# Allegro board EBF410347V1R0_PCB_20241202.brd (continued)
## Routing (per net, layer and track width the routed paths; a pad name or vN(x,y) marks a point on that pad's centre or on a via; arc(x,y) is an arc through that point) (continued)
UART4_TX_M0: length 81.6
  TOP w0.173: v1(106.78,44.14) R128.1 107.38,44.91 D72.1 108.69,43.6 110.19,43.6 110.56,43.22 U25.11 ; J3.68 66.79,67.7 66.4,67.31 v1(66.4,67.26)
  ART03 w0.16: v1(65.47,48.61) 64.79,48.61 64.47,48.93 64.47,66.06 65.17,66.77 65.91,66.77 v1(66.4,67.26)
  BOTTOM w0.173: v1(65.47,48.61) 65.45,48.64 64.59,48.64 64.26,48.31 64.26,45.52 64.44,45.34 67.39,45.34 67.59,45.54 67.59,46.23 67.76,46.4 89.1,46.4 89.89,45.62 92.91,45.62 93.75,44.78 93.75,42.8 94.16,42.39 101.45,42.39 101.83,42.77 101.83,43.84 102.14,44.14 v1(106.78,44.14)
UART7_RX_M0: length 75.4
  TOP w0.173: U25.9 113.1,44.21 D69.1 112.46,44.91 R123.1 v1(111.86,44.14) ; v1(66.35,66.27) 66.35,66.56 65.89,67.03 J3.69
  ART03 w0.16: v1(65.47,49.61) 65.47,65.32 66.35,66.2 v1(66.35,66.27)
  BOTTOM w0.173: v1(65.47,49.61) 66.44,49.61 67.44,48.61 108.94,48.61 109.68,47.88 110.7,47.88 111.2,47.37 111.2,44.8 v1(111.86,44.14)
UART7_TX_M0: length 76.2
  TOP w0.173: U25.10 111.84,42.99 D70.1 109.92,44.91 R124.1 v1(109.32,44.14) ; J3.70 64.99,67.63 v1(65.35,67.27)
  ART03 w0.16: v1(65.35,67.27) 65.13,67.27 64.06,66.19 64.06,48.53 64.48,48.11 65.97,48.11 v1(66.47,48.61)
  BOTTOM w0.173: v1(66.47,48.61) 66.83,48.26 107.9,48.26 108.28,47.88 108.28,46.61 109.32,45.57 v1(109.32,44.14)
UART8_RX_M0: length 99.5
  TOP w0.173: J3.71 64.09,67.54 63.8,67.26 62.22,67.26 v1(62.21,67.25)
  ART03 w0.16: v1(97.12,12.57) 93.79,12.57 93.47,12.89 93.47,15.75 93.09,16.13 67.82,16.13 67.41,15.72 64.41,15.72 64.06,16.08 64.06,25.35 61.79,27.61 61.79,66.54 62.21,66.96 v1(62.21,67.25)
  BOTTOM w0.173: v1(97.12,12.57) 97.66,13.11 99.28,13.11 R115.1
  BOTTOM w0.254: U24.1 D60.1 99.81,11.85 R115.1
UART8_TX_M0: length 94.4
  TOP w0.173: J3.72 63.19,68.45 v1(63.39,68.25)
  ART03 w0.16: v1(97.1,17.76) 83.42,17.76 82.35,16.69 64.83,16.69 64.51,17.01 64.51,25.61 62.31,27.81 62.31,66.61 63.39,67.7 v1(63.39,68.25)
  BOTTOM w0.173: v1(97.1,17.76) 99.51,17.76 99.81,17.46 R117.1
  BOTTOM w0.254: R117.1 99.81,16.04 D61.1 100.87,14.98 U24.4
UART9_RX_M1: length 84.8
  TOP w0.173: v1(61.21,67.25) 61.39,67.25 62.29,68.15 J3.73
  ART03 w0.16: v1(82.69,12.57) 82.69,13.44 82.19,13.94 71.07,13.94 70.73,13.6 69.81,13.6 69.39,14.02 68.17,14.02 67.94,13.79 63.68,13.79 63.12,14.35 63.12,17.78 62.64,18.26 62.64,25.35 60.79,27.19 60.79,66.81 61.21,67.23 v1(61.21,67.25)
  BOTTOM w0.173: R125.1 84.95,13.11 83.23,13.11 v1(82.69,12.57)
  BOTTOM w0.254: R125.1 85.49,11.85 D67.1 U26.1
UART9_TX_M1: length 82.7
  TOP w0.173: v1(61.21,68.25) 61.39,68.43 J3.74
  ART03 w0.16: v1(82.93,15.37) 68.2,15.37 67.49,14.65 63.96,14.65 63.64,14.97 63.64,25.08 61.28,27.44 61.28,66.59 61.72,67.03 61.72,67.72 61.21,68.23 v1(61.21,68.25)
  BOTTOM w0.173: v1(82.93,15.37) 82.93,15.87 83.19,16.13 84.85,16.13 R127.1
  BOTTOM w0.254: U26.4 86.54,14.98 D68.1 86.16,16.09 R127.1
USB20_HOST1_DM: length 55.3
  TOP w0.132: J3.94 43.39,70.45 43.72,70.78 43.72,71.23 44.06,71.58 91.87,71.58 92.53,70.92 92.53,67.31 R65.2
USB20_HOST1_DP: length 55.4
  TOP w0.132: R64.2 92.29,67.31 92.29,70.82 91.77,71.34 91.46,71.34 91.24,71.12 90.93,71.12 90.72,71.34 90.41,71.34 90.19,71.12 89.88,71.12 89.66,71.34 89.35,71.34 89.13,71.12 88.82,71.12 88.6,71.34 88.29,71.34 88.07,71.12 87.76,71.12 87.55,71.34 87.24,71.34 87.02,71.12 86.71,71.12 86.49,71.34 44.16,71.34 43.96,71.14 43.96,70.78 44.29,70.45 J3.93
USB20_HUB_PWR_EN: length 35.9
  TOP w0.173: J3.42 82.76,60.3 v1(82.65,60.19) ; R67.1 v1(110.31,53.2)
  BOTTOM w0.173: v1(110.31,53.2) 109.54,53.97 105.28,53.97 104.77,53.46 96.83,53.46 96.14,54.15 92.86,54.15 92.46,54.56 92.46,55.88 92.13,56.21 83.87,56.21 83.36,56.72 83.36,59.48 v1(82.65,60.19)
USB30_DM: length 18.8
  BOTTOM w0.132: R52.1 72.7,67.54 72.84,67.67 72.84,69.91 72.67,70.08 ; 72.67,70.08 72.84,70.25 72.84,71.33 72.71,71.46 70.97,71.46 70.56,71.87 70.56,75.37 71.61,76.42 75.93,76.42 76.29,76.06 76.29,75.3 76.42,75.17 J9.2 ; 72.67,70.08 D17.1
USB30_DP: length 18.6
  BOTTOM w0.132: 73.25,70.08 73.08,69.91 73.08,67.67 73.21,67.54 R53.1 ; 73.25,70.08 73.08,70.24 73.08,71.43 72.81,71.7 72.33,71.7 72.12,71.91 71.75,71.91 71.54,71.7 71.07,71.7 70.8,71.97 70.8,72.25 70.99,72.44 70.99,72.78 70.8,72.97 70.8,73.31 70.99,73.5 70.99,73.84 70.8,74.03 70.8,75.27 71.71,76.18 75.83,76.18 76.05,75.96 76.05,75.3 75.92,75.17 J9.3 ; 73.25,70.08 D18.1
USB30_OTG0_DM: length 50.5
  TOP w0.132: J3.97 40.69,68.54 41.02,68.21 41.02,67.08 41.38,66.72 44.82,66.72 45.09,66.46 45.09,60.71 45.55,60.24 73.99,60.24 v1(74.37,59.86)
  BOTTOM w0.132: R52.2 72.26,66.09 72.4,65.95 72.71,65.95 72.84,65.82 72.84,60.52 73.13,60.24 73.99,60.24 v1(74.37,59.86)
USB30_OTG0_DP: length 50.8
  TOP w0.132: J3.96 41.59,68.54 41.26,68.21 41.26,67.18 41.48,66.96 44.92,66.96 45.32,66.56 45.32,60.8 45.65,60.48 74.24,60.48 74.37,60.61 v1(74.37,60.86)
  BOTTOM w0.132: R53.2 73.66,66.09 73.53,65.95 73.21,65.95 73.08,65.82 73.08,64.8 73.3,64.58 73.3,64.28 73.08,64.05 73.08,63.75 73.3,63.52 73.3,63.22 73.08,63 73.08,62.69 73.3,62.47 73.3,62.16 73.08,61.94 73.08,61.63 73.3,61.41 73.3,61.11 73.08,60.88 73.08,60.62 73.23,60.48 74.24,60.48 74.37,60.61 v1(74.37,60.86)
USB30_OTG0_ID: length 54.3
  TOP w0.173: J3.99 38.89,72.58 39.23,72.92 47.69,72.92 48.67,73.9 48.67,76.77 48.98,77.09 51.93,77.09 52.63,77.79 52.63,80.44 54.14,81.95 81.13,81.95 v1(81.9,81.19)
  BOTTOM w0.173: v1(81.9,81.19) 81.92,81.2 R193.2
USB30_OTG0_SSRXN: length 37.5
  TOP w0.132: v1(75.07,63.16) 48.62,63.16 48.22,63.56 48.22,68.21 47.89,68.54 J3.89
  BOTTOM w0.132: R54.2 74.8,66.09 74.94,65.95 75.25,65.95 75.38,65.82 75.38,65.56 75.16,65.34 75.16,65.03 75.38,64.81 75.38,64.51 75.16,64.28 75.16,63.98 75.38,63.75 75.38,63.29 75.25,63.16 v1(75.07,63.16)
USB30_OTG0_SSRXP: length 37.8
  TOP w0.132: J3.88 48.79,68.54 48.46,68.21 48.46,63.66 48.72,63.4 74.64,63.4 74.89,63.64 75.27,63.64 75.75,63.16 v1(75.93,63.16)
  BOTTOM w0.132: v1(75.93,63.16) 75.62,63.47 75.62,65.82 75.75,65.95 76.07,65.95 76.2,66.09 R55.2
USB30_OTG0_SSTXN: length 45.9
  TOP w0.132: v1(77.56,62.65) 77.87,62.96 77.87,63.31 77.74,63.44 77.09,63.44 76.92,63.27 76.92,62.09 76.49,61.66 46.82,61.66 46.42,62.06 46.42,68.21 46.09,68.54 J3.91
  BOTTOM w0.132: C63.2 77.34,66.09 77.48,65.95 77.74,65.95 77.89,65.8 77.89,62.98 v1(77.56,62.65)
USB30_OTG0_SSTXP: length 45.9
  TOP w0.132: J3.90 46.99,68.54 46.66,68.21 46.66,62.16 46.92,61.9 76.39,61.9 76.68,62.19 76.68,63.37 76.99,63.68 77.84,63.68 78.11,63.4 78.11,62.96 v1(78.42,62.65)
  BOTTOM w0.132: C64.2 78.74,66.09 78.61,65.95 78.31,65.95 78.13,65.77 78.13,62.94 v1(78.42,62.65)
USB30_OTG0_VBUSDET: length 54.9
  TOP w0.173: v1(79.88,83.63) 79.31,83.06 74.12,83.06 73.63,82.57 53.87,82.57 52.04,80.75 52.04,78.03 51.69,77.67 48.74,77.67 48.08,77.01 48.08,74.14 47.45,73.51 38.33,73.51 37.99,73.16 J3.100
  BOTTOM w0.173: v1(79.88,83.63) R58.2 R59.1
USB30_OTG_PWR_EN: length 58.6
  TOP w0.173: J3.41 85.08,59.4 86.02,60.34 86.02,62.98 86.34,63.3 v1(86.34,67.69)
  ART03 w0.16: v1(72.14,81.29) 72.17,81.29 72.76,80.69 74.6,80.69 76.25,82.35 95.58,82.35 96.42,81.51 96.42,78.18 95.12,76.88 95.12,71.93 94.54,71.35 86.94,71.35 86.78,71.19 86.78,68.12 v1(86.34,67.69)
  BOTTOM w0.173: R56.1 v1(72.14,81.29)
USB30_OTG_VBUS: length 5.7
  BOTTOM w0.762: J9.1 79.67,80.82
USB30_RXN: length 10.1
  BOTTOM w0.132: J9.5 72.92,73.67 73.05,73.54 73.05,72.52 73.56,72.01 73.98,72.01 74.21,71.78 74.58,71.78 74.81,72.01 75.21,72.01 75.38,71.84 75.38,70.21 75.25,70.08 ; 75.25,70.08 D19.1 ; 75.25,70.08 75.39,69.94 75.39,67.7 75.23,67.54 R54.1
USB30_RXP: length 9.9
  BOTTOM w0.132: D20.1 75.75,70.08 ; 75.75,70.08 75.63,69.96 75.63,67.67 75.76,67.54 R55.1 ; 75.75,70.08 75.62,70.21 75.62,71.94 75.31,72.25 73.66,72.25 73.29,72.62 73.29,73.54 73.42,73.67 J9.6
USB30_TXN: length 8.8
  BOTTOM w0.132: D21.1 77.78,70.08 ; 77.78,70.08 77.92,69.95 77.92,67.67 77.78,67.54 C63.1 ; 77.78,70.08 77.79,70.08 77.92,70.21 77.92,71.68 78.36,72.12 78.87,72.12 79.05,72.3 79.05,73.54 78.92,73.67 J9.8
USB30_TXP: length 8.8
  BOTTOM w0.132: 78.29,70.08 78.16,70.21 78.16,71.58 78.46,71.88 78.97,71.88 79.29,72.21 79.29,73.54 79.42,73.67 J9.9 ; 78.29,70.08 78.29,70.08 78.16,69.95 78.16,67.67 78.29,67.54 C64.1 ; 78.29,70.08 D22.1
USB_HUB_3V3: length 23.1
  TOP w0.254: v1(87.84,67.66) R62.2 R61.2 88.85,68.07 89.08,68.3 90.55,68.3 90.88,67.97 R63.2 ; 88.84,62.52 v1(88.84,63.9)
  TOP w0.305: U8.20 89.2,62.16 88.84,62.52 ; U8.1 90.65,58.18 C70.1 C69.1 R60.2
  TOP w0.381: R60.2 C71.1 88.47,62.16 88.84,62.52
  BOTTOM w0.254: v1(87.84,67.66) 88.84,66.66 v1(88.84,63.9)
USB_HUB_DM1: length 20.6
  TOP w0.132: J12.2 100.26,75.62 100.26,72.45 D24.1 100.26,71.3 100.26,69.5 99.87,69.1 96.79,69.1 96.32,68.63 96.32,62.69 95.92,62.29 94.78,62.29 94.65,62.16 U8.11
USB_HUB_DM2: length 54.6
  TOP w0.132: U8.9 94.65,61.16 94.78,61.29 97.17,61.29 97.63,61.74 97.63,63.44 v1(97.94,63.75)
  BOTTOM w0.132: J13.2 117.27,77.33 117.27,79.72 D26.1 117.81,80.35 117.22,80.93 117.22,82.35 116.82,82.74 115.5,82.74 115.08,82.32 115.08,78.38 114.8,78.1 112.75,78.1 112.01,77.37 112.01,74.47 111.72,74.18 98.15,74.18 98.14,74.17 96.82,74.17 96.14,73.48 96.14,63.19 96.5,62.83 97.33,62.83 97.63,63.12 97.63,63.44 v1(97.94,63.75)
USB_HUB_DM3: length 34.9
  TOP w0.132: U8.7 94.65,60.16 94.78,60.29 96.6,60.29 96.87,60.02 96.87,55.11 97.27,54.71 98.02,54.71 v1(98.33,54.4) ; 117.93,53.34 117.79,53.47 115.81,53.47 v1(115.5,53.16) ; 117.93,53.34 D28.1 ; 117.93,53.34 118.06,53.47 120.92,53.47 121.09,53.3 J14.3
  BOTTOM w0.132: v1(115.5,53.16) 115.19,53.47 114.62,53.47 113.38,54.71 98.64,54.71 v1(98.33,54.4)
USB_HUB_DM4: length 52.5
  TOP w0.132: v1(109.98,38.11) 110.28,38.4 113.85,38.4 114.28,38.84 114.28,40.92 114.58,41.22 117.79,41.22 117.93,41.09 ; 117.93,41.09 118.06,41.22 120.92,41.22 121.09,41.05 J38.3 ; 117.93,41.09 D38.1 ; v1(102.57,40.99) 102.27,41.29 101.94,41.29 101.67,41.56 101.67,50.56 101.4,50.82 96.2,50.82 95.93,51.1 95.93,57.51 95.76,57.67 93.34,57.67 92.78,58.23 92.78,58.52 92.65,58.65 U8.5
  ART03 w0.114: v1(102.57,40.99) 102.88,41.3 105.04,41.3 105.27,41.07 105.27,38.84 105.69,38.42 109.68,38.42 v1(109.98,38.11)
USB_HUB_DP1: length 20.5
  TOP w0.132: U8.12 94.65,62.65 94.78,62.52 95.82,62.52 96.08,62.79 96.08,68.73 96.69,69.34 99.77,69.34 100.03,69.59 100.03,71.29 D25.1 100.02,72.45 100.02,76.13 99.65,76.5 J12.3
USB_HUB_DP2: length 54.5
  TOP w0.132: U8.10 94.65,61.65 94.78,61.52 97.07,61.52 97.39,61.84 97.39,63.6 97.23,63.75 v1(97.08,63.75)
  BOTTOM w0.132: v1(97.08,63.75) 97.25,63.75 97.39,63.62 97.39,63.22 97.23,63.07 96.6,63.07 96.38,63.29 96.38,65.84 96.57,66.03 96.57,66.37 96.38,66.56 96.38,66.9 96.57,67.09 96.57,67.43 96.38,67.62 96.38,67.95 96.57,68.15 96.57,68.48 96.38,68.68 96.38,69.01 96.57,69.2 96.57,69.54 96.38,69.73 96.38,70.07 96.57,70.26 96.57,70.6 96.38,70.79 96.38,71.12 96.57,71.32 96.57,71.65 96.38,71.85 96.38,72.18 96.57,72.37 96.57,72.71 96.38,72.9 96.38,73.38 96.92,73.93 97.44,73.93 97.66,73.71 98.02,73.71 98.25,73.94 111.82,73.94 112.25,74.37 112.25,77.27 112.85,77.87 114.9,77.87 115.32,78.28 115.32,82.22 115.6,82.51 116.72,82.51 116.98,82.25 116.98,80.83 D27.1 116.41,80.26 117.03,79.64 117.03,76.8 116.73,76.5 J13.3
USB_HUB_DP3: length 34.9
  TOP w0.132: v1(115.5,54.02) 115.81,53.71 117.79,53.71 117.93,53.84 ; J14.2 121.09,53.84 120.96,53.71 118.06,53.71 117.93,53.84 ; 117.93,53.84 D29.1 ; v1(98.33,55.26) 98.02,54.95 97.37,54.95 97.11,55.21 97.11,60.12 96.7,60.52 94.78,60.52 94.65,60.65 U8.8
  BOTTOM w0.132: v1(115.5,54.02) 115.19,53.71 114.72,53.71 113.48,54.95 98.64,54.95 v1(98.33,55.26)
USB_HUB_DP4: length 52.4
  TOP w0.132: v1(109.98,38.97) 109.98,38.77 110.12,38.64 113.75,38.64 114.05,38.94 114.05,41.02 114.48,41.46 117.79,41.46 117.93,41.59 ; 117.93,41.59 118.06,41.46 120.96,41.46 121.09,41.59 J38.2 ; 117.93,41.59 D73.1 ; v1(102.57,41.85) 102.25,41.53 102.04,41.53 101.9,41.66 101.9,50.66 101.5,51.06 96.3,51.06 96.16,51.2 96.16,57.61 95.86,57.91 93.44,57.91 93.02,58.33 93.02,58.52 93.15,58.65 U8.6
  ART03 w0.114: v1(102.57,41.85) 102.57,41.67 102.71,41.54 105.14,41.54 105.51,41.17 105.51,38.94 105.79,38.66 109.86,38.66 109.98,38.79 v1(109.98,38.97)
WL_HOST_WAKE: length 26.4
  TOP w0.173: J3.49 81.34,66.6 81,66.25 v1(81,62.61) ; R166.1 v1(98.3,64.9)
  ART03 w0.16: v1(81,62.61) 81.18,62.79 92.25,62.79 93.73,64.26 95.86,64.26 97,65.4 97.79,65.4 v1(98.3,64.9)
WL_REG_ON: length 28
  TOP w0.173: J3.48 81.88,65.7 81.53,65.35 81.53,62.14 v1(81,61.61) ; R165.1 97.61,66.93 97.33,66.64 v1(97.33,64.9)
  ART03 w0.16: v1(97.33,64.9) 96.28,63.85 94.08,63.85 92.61,62.38 81.77,62.38 v1(81,61.61)
N16722129: length 8.4
  TOP w0.254: U2.4 27.37,64.83 26.8,64.26 26.8,63.24 v1(27.33,62.7)
  BOTTOM w0.254: R5.1 C12.1 26.92,59.82 R9.1 26.67,61.08 26.67,62.04 v1(27.33,62.7)
N16722243: length 7.5
  TOP w0.173: v1(27.33,63.7) 27.51,63.88 U2.5
  BOTTOM w0.173: v1(27.33,63.7) 25.96,63.7 25.65,64.01 25.65,65.4 25.4,65.66 R7.1 R8.1
N16722849: length 18.9
  BOTTOM w0.508: J1.5 20.15,80.91 19.71,80.47 L2.1 17.95,79.63 11.68,79.63 10.35,80.96 J1.1
N16722969: length 3.9
  TOP w0.254: U4.4 v1(18.11,64.83)
  BOTTOM w0.254: v1(18.11,64.83) 18.18,64.9 R17.1 18.8,63.63 R14.1 C25.1
N16723631: length 4.5
  TOP w0.254: U1.4 v1(10.51,64.83)
  BOTTOM w0.254: R1.1 C2.1 R4.1 9.33,64.83 v1(10.51,64.83)
N16724039: length 5
  TOP w0.173: U3.5 21.7,63.88 v1(21.65,63.83)
  BOTTOM w0.173: R10.1 22.35,61.58 22.35,63.12 21.65,63.82 v1(21.65,63.83)
N16724163: length 4.8
  TOP w0.254: U3.4 v1(24.05,64.83)
  BOTTOM w0.254: C15.1 R6.1 R11.1 23.1,64.62 23.3,64.83 v1(24.05,64.83)
N16724623: length 8.2
  TOP w0.173: LED2.2 v1(9.1,85.4)
  BOTTOM w0.173: v1(9.1,85.4) 8.79,85.09 8.79,81.86 8.53,81.61 6.91,81.61 6.61,81.31 R13.2
N16724791: length 6.9
  TOP w0.254: LED1.2 v1(4.37,85.4)
  BOTTOM w0.173: v1(4.37,85.4) 3.52,84.55 R12.2
N16783121: length 5.7
  TOP w0.173: J7.1 v1(56.29,73.1)
  BOTTOM w0.173: R43.2 55.41,76.29 55.41,74.57 D7.1 55.95,73.44 v1(56.29,73.1)
N16783123: length 5.7
  TOP w0.173: v1(62.89,73.1) J7.7
  BOTTOM w0.173: R47.2 63.41,76.22 63.41,74.64 D3.1 62.8,73.19 v1(62.89,73.1)
N16783125: length 6
  TOP w0.173: v1(60.69,73.1) J7.5
  BOTTOM w0.173: v1(60.69,73.1) 61.62,74.03 D4.1 62.25,74.62 62.25,76.24 R46.2
N16783127: length 5.7
  TOP w0.173: v1(58.49,73.1) J7.3
  BOTTOM w0.173: v1(58.49,73.1) 58.23,73.36 D5.1 57.68,74.58 57.68,76.28 R45.2
N16783129: length 5.7
  TOP w0.173: J7.2 v1(57.39,73.1)
  BOTTOM w0.173: R44.2 56.55,76.29 56.55,74.57 D6.1 57.09,73.4 v1(57.39,73.1)
N16783131: length 5.6
  TOP w0.173: J7.8 v1(63.99,73.1)
  BOTTOM w0.173: v1(63.99,73.1) 63.95,73.14 D2.1 64.49,74.57 64.49,76.29 R48.2
N16783147: length 5.6
  TOP w0.173: J7.9 v1(65.09,73.1)
  BOTTOM w0.173: R49.2 65.65,76.27 65.65,74.59 D1.1 v1(65.09,73.1)
N16783231: length 3.6
  BOTTOM w0.254: R41.2 87.96,75.73 87.96,73.73 J6.1
N16783233: length 3.6
  BOTTOM w0.254: R42.2 88.37,75.78 88.37,73.68 J6.2
N16783279: length 1.2
  TOP w0.381: U5.6 v1(13.84,37.46)
N16783471: length 1.2
  TOP w0.381: U6.6 v1(12.57,44.19)
N16783658: length 4.7
  TOP w0.173: U5.1 v1(11.3,29.84)
  BOTTOM w0.173: v1(11.3,29.84) 11.18,29.97 R25.2 11.18,30.74 11.81,31.37 11.81,32.14 R28.1
N16783744: length 2.5
  TOP w0.254: v1(14.57,29.84) 14.76,29.84 15.11,30.2 U5.4
  BOTTOM w0.254: R22.2 14.48,29.94 v1(14.57,29.84)
N16783769: length 2.5
  TOP w0.173: v1(13.3,29.84) 13.5,29.84 13.84,30.19 U5.3
  BOTTOM w0.173: R24.2 13.46,30 v1(13.3,29.84)
N16783771: length 1
  BOTTOM w0.254: R22.1 C34.2
N16783785: length 1
  BOTTOM w0.173: C35.2 R24.1
N16783804: length 2.1
  TOP w0.381: L7.1 11.3,38.19 U5.8
N16783806: length 2.1
  TOP w0.381: U5.5 15.11,38.19 L6.1
N16783823: length 2.3
  TOP w0.173: v1(12.3,29.84) 12.57,30.11 U5.2
  BOTTOM w0.173: v1(12.3,29.84) 12.45,29.99 C39.1
N16783940: length 5.1
  TOP w0.173: U6.1 v1(15.11,51.66)
  BOTTOM w0.173: v1(15.11,51.66) 15.67,52.22 17.77,52.22 R40.1 R39.2
N16784027: length 2
  TOP w0.254: U6.4 v1(11.3,51.66)
  BOTTOM w0.254: R35.2 11.23,51.74 v1(11.3,51.66)
N16784039: length 2.4
  TOP w0.173: U6.3 v1(12.57,51.66)
  BOTTOM w0.173: v1(12.57,51.66) 12.95,52.04 R37.2
N16784051: length 1.1
  BOTTOM w0.254: C46.2 9.41,52.83 R35.1
N16784053: length 1
  BOTTOM w0.173: R37.1 C47.2
N16784084: length 2.1
  TOP w0.381: U6.8 15.11,43.47 L9.1
N16784086: length 2.1
  TOP w0.381: U6.5 11.3,43.47 L8.1
N16784100: length 2.3
  TOP w0.173: U6.2 v1(13.84,51.66)
  BOTTOM w0.173: v1(13.84,51.66) 13.97,51.79 C51.1
N16784225: length 5.3
  BOTTOM w0.173: R36.1 R31.1 C50.1 47.43,84.44 J5.6
N16784316: length 15
  BOTTOM w0.254: R23.1 C36.1 R26.1 R20.2 49.45,80.37 49.17,80.65 49.17,82.69 48.84,83.02 46.84,83.02 45.85,84.01 43.1,84.01 42.8,84.31 J5.1
N16784333: length 2
  BOTTOM w0.173: R20.1 C33.1 R18.1
N16784429: length 6.3
  BOTTOM w0.254: J5.3 44.2,78.3 R34.1
N16784431: length 5.8
  BOTTOM w0.254: R33.1 46.23,78.13 J5.4
N16786732: length 3.1
  TOP w0.173: U4.5 16.2,63.88 v1(16.15,63.83)
  BOTTOM w0.173: R3.1 R2.1 17.09,63.83 v1(16.15,63.83)
N16786936: length 3.7
  TOP w0.173: v1(10.51,63.83) 10.56,63.88 U1.5
  BOTTOM w0.173: R15.1 9.91,62.49 9.91,63.22 v1(10.51,63.83)
N16788412: length 1.5
  BOTTOM w0.114: C54.2 T1.4
N16788414: length 1.5
  BOTTOM w0.114: C55.2 T1.1
N16788463: length 1.5
  BOTTOM w0.114: C56.2 T3.4
N16788475: length 1.5
  BOTTOM w0.114: C57.2 T3.1
N16788524: length 1.5
  BOTTOM w0.114: C58.2 T5.4
N16788526: length 1.5
  BOTTOM w0.114: C59.2 T5.1
N16788585: length 1.5
  BOTTOM w0.114: C60.2 T7.4
N16788587: length 1.5
  BOTTOM w0.114: C61.2 T7.1
N16792936: length 5.6
  BOTTOM w0.173: R16.1 26.29,75.19 25.94,75.54 25.31,75.54 J10.9
N16792940: length 46.7
  ART04 w0.508: J10.14 39.62,81.68 39.62,75.46 38.86,74.7 36.93,74.7 36.3,74.07 36.3,72.52 35.79,72.01 27.03,72.01 26.62,72.41 26.62,74.47 26.11,74.98 23.62,74.98 23.11,75.49 23.11,81.71 J10.13
  BOTTOM w0.508: J10.13 23.36,78.35 22.73,77.72 R51.2 20.57,72.52 C62.2
N16793616: length 5.9
  BOTTOM w0.173: R50.1 38.48,75.07 38.14,75.41 37.27,75.41 J10.11
N16801073: length 17.7
  TOP w0.508: J9.11 J9.10
  BOTTOM w0.508: L10.2 69.6,77.18 J9.11
N16801211: length 5
  BOTTOM w0.173: R56.2 C65.1 73.28,84.54 73.46,84.72 74.42,84.72 74.63,84.51 74.63,83.67 U7.4
N16801228: length 6.2
  BOTTOM w0.173: U7.3 74.61,80.39 74.37,80.15 71.3,80.15 70.99,80.45 R57.1
N16802593: length 11.8
  BOTTOM w0.173: R193.1 82.94,82.92 83.31,82.55 D23.1 84.55,81.25 85.22,81.91 89.03,81.91 89.41,82.29 J11.1
N16803235: length 2.6
  TOP w0.132: U8.15 92.15,64.16 92.28,64.29 92.28,65.54 R64.1
N16803237: length 2.6
  TOP w0.132: R65.1 92.52,65.52 92.52,64.29 92.65,64.16 U8.14
N16803510: length 7.1
  TOP w0.173: U8.3 91.65,57.86 C73.1 91.73,56.86 91.73,53.61 91.6,53.48 Y1.1
N16803514: length 5.7
  TOP w0.173: U8.4 92.15,57.88 C74.1 92.05,56.81 92.05,55.12 92.2,54.98 Y1.3
N16803540: length 2.7
  TOP w0.173: R66.1 93.15,65.14 U8.13
N16803549: length 4
  TOP w0.173: R61.1 C72.1 91.15,64.64 U8.17
N16803553: length 2.7
  TOP w0.173: U8.16 91.65,65.15 R63.1
N16803559: length 4.5
  TOP w0.173: R62.1 88.37,65.38 89.95,65.38 90.65,64.68 U8.18
N16804913: length 20.2
  TOP w0.508: J12.5 J12.6 93.6,79.19 L11.2
N16810803: length 3.4
  TOP w0.173: R67.2 C77.1 111.46,50.04 111.27,49.84 U9.4
N16810815: length 2.5
  TOP w0.173: U9.3 112.18,49.84 112.04,49.99 112.04,50.37 R68.1
N16816847: length 5.2
  BOTTOM w0.203: R72.1 94.3,31.84 D33.1 91.66,30.59 J16.2
N16816849: length 4.8
  BOTTOM w0.173: J16.1 89.66,31.51 D32.1 91.38,31.84 R71.1
N16821329: length 5.9
  TOP w0.173: C89.1 30.66,28.07 30.31,28.41 U10.11
  TOP w0.254: v1(30.4,29.08) C90.1 C89.1
  BOTTOM w0.254: C89.1 C90.1 v1(30.4,29.08)
N16823430: length 6.2
  TOP w0.173: R83.2 R85.1 19.31,30.99 20.32,30.99 20.83,30.48 22.4,30.48 22.65,30.23 U10.24
N16823432: length 1.5
  TOP w0.173: Y2.3 16.93,31.91 R83.1
N16823570: length 2.6
  TOP w0.173: R76.2 30.66,26.03 29.78,26.91 U10.8
N16823572: length 3.2
  TOP w0.173: U10.7 29.75,26.41 30.2,25.96 30.2,25.32 30.5,25.02 R77.2
N16823879: length 2.5
  TOP w0.173: U10.1 30.7,23.41 R74.2
N16823895: length 2.3
  TOP w0.173: U10.2 31.03,23.91 R75.2
N16825657: length 4
  TOP w0.173: J26.2 v1(62.15,18.41)
  BOTTOM w0.173: v1(62.15,18.41) 61.22,18.41 D53.1 R139.1
N16825664: length 4
  TOP w0.173: J26.3 v1(60.15,18.41)
  BOTTOM w0.173: v1(60.15,18.41) 59.19,18.41 D52.1 R140.1
N16825671: length 4
  TOP w0.173: J26.4 v1(58.15,18.41)
  BOTTOM w0.173: v1(58.15,18.41) 57.16,18.41 D51.1 R141.1
N16825678: length 4.1
  TOP w0.173: J26.5 v1(56.15,18.41)
  BOTTOM w0.173: v1(56.15,18.41) 55.13,18.41 D50.1 R142.1
N16825685: length 4
  TOP w0.173: J26.6 v1(54.15,18.41)
  BOTTOM w0.173: v1(54.15,18.41) 54.14,18.41 D49.1 R143.1
N16825692: length 4
  TOP w0.173: J26.7 v1(52.15,18.41)
  BOTTOM w0.173: R144.1 D48.1 51.19,18.41 v1(52.15,18.41)
N16827764: length 4.9
  BOTTOM w0.173: R145.1 D59.1 103.58,29.66 J27.2
N16827766: length 4.8
  BOTTOM w0.173: J27.3 105.87,29.38 D58.1 R146.1
N16827768: length 4.6
  BOTTOM w0.173: R147.1 D57.1 108.16,29.09 J27.4
N16827770: length 4.5
  BOTTOM w0.173: J27.5 110.44,28.81 D56.1 R148.1
N16827772: length 4.5
  BOTTOM w0.173: R149.1 D55.1 112.73,28.63 J27.6
N16832694: length 4.5
  TOP w0.394: U16.2 C120.1 112.27,70.86 C114.2
N16832701: length 2.2
  TOP w0.394: CN1.1 115.33,70.86 C115.1 115.31,70.86 C114.1
N16832725: length 3.8
  TOP w0.254: U16.6 108.66,68.96 109.55,69.85 R156.2
N16832727: length 3.8
  TOP w0.173: R158.2 108.54,69.98 107.76,69.2 U16.7
N16832815: length 3.5
  TOP w0.173: U16.12 100.15,65.91 R164.2 R165.2
N16832856: length 2.6
  TOP w0.173: R166.2 100.26,65 U16.13
N16833042: length 2.4
  TOP w0.173: R162.2 R163.1 105.87,49.78 Y4.3
N16833048: length 3.3
  TOP w0.173: U16.24 105.06,52.4 R162.1
N16833114: length 3.3
  TOP w0.173: U16.34 116.92,56.9 R151.2 R155.1
N16853010: length 6.2
  BOTTOM w0.173: D45.1 D46.1 110.27,64.63 R130.2 111.2,62.7 110.92,62.41 U15.3
N16853145: length 4.2
  BOTTOM w0.173: Y3.2 106.59,61.6 107.16,61.6 C119.1 107.73,61.76 U15.2
N16853170: length 4.3
  BOTTOM w0.173: Y3.1 106.57,61.28 107.1,61.28 C118.1 107.77,61.11 U15.1
N16853193: length 5.3
  BOTTOM w0.173: R135.1 R131.2 112.22,62.06 112.52,61.76 U15.7
N16853900: length 6.3
  BOTTOM w0.381: Q2.3 123.52,53.87 123.21,53.55 Q1.1 123.21,51 R136.2
N16853902: length 2.9
  BOTTOM w0.173: R137.2 R138.1 127.14,51 Q2.1
N16853946: length 8.7
  BOTTOM w0.381: R134.2 123.95,56.56 D47.1 125.99,58.04 126.39,58.44 J25.1
N16853981: length 4.4
  BOTTOM w0.381: Q1.2 121.3,51 R136.1 121.45,50.24 R132.2 R133.2
N16854018: length 2.9
  BOTTOM w0.381: R134.1 121.24,54.13 121.49,53.87 Q1.3
N16869660: length 1.9
  TOP w0.173: U25.3 C151.1
N16869662: length 3.2
  TOP w0.173: U25.1 104.22,34.66 104.55,34.34 C151.2
N16869664: length 1.9
  TOP w0.173: C152.1 109.3,34.51 U25.5
N16869666: length 1.9
  TOP w0.173: C152.2 108.02,34.45 U25.4
N16869668: length 1.9
  TOP w0.173: U25.6 C155.1
N16869670: length 6.9
  TOP w0.173: C154.1 103.32,37.51 103.63,37.82 105.21,37.82 105.48,37.54 U25.2
N16869989: length 4.8
  BOTTOM w0.173: R119.2 95.02,16.48 94.74,16.76 D66.1
N16870097: length 5.1
  BOTTOM w0.173: D54.1 109.45,16.76 109.6,16.61 R109.2
N16870438: length 1.9
  TOP w0.173: U23.3 C148.1
N16870440: length 3.2
  TOP w0.173: C148.2 90.88,34.34 90.58,34.64 U23.1
N16870442: length 1.9
  TOP w0.173: C149.1 95.66,34.45 U23.5
N16870444: length 1.9
  TOP w0.173: C149.2 94.38,34.51 U23.4
N16870446: length 1.9
  TOP w0.173: U23.6 C147.1
N16870448: length 6.7
  TOP w0.173: C146.1 89.74,37.44 90.07,37.77 91.54,37.77 91.84,37.47 U23.2
N16880008: length 2
  TOP w0.173: U27.4 v1(12.99,28.51)
  BOTTOM w0.173: C162.1 13.43,28.07 v1(12.99,28.51)
N16948483: length 17.9
  TOP w0.508: J13.6 J13.5
  BOTTOM w0.508: L12.2 110.58,79.26 J13.6
N16990717: length 4.7
  TOP w0.173: J21.1 v1(80.4,14.5)
  BOTTOM w0.173: v1(80.4,14.5) 80.4,12.7 D39.1 R98.2
N16990719: length 4.8
  TOP w0.173: J21.3 v1(76.4,14.5)
  BOTTOM w0.173: v1(76.4,14.5) 76.4,12.74 D40.1 R103.2
N16990803: length 6.5
  TOP w0.173: J21.6 v1(70.4,14.27)
  BOTTOM w0.173: v1(70.4,14.27) 70.4,13.04 70.75,12.69 D41.1 R108.2
N16991546: length 3.9
  TOP w0.173: U17.21 19.78,39.78 R188.2
N17000237: length 2.2
  TOP w0.173: U21.4 18.91,45.74 19.2,46.02 19.74,46.02 R215.1
N17000272: length 2.1
  TOP w0.173: R216.1 19.59,50.95 19.13,50.95 18.91,50.74 U22.4
N17004192: length 8.4
  TOP w0.173: U13.4 13.03,21.27 v1(13.08,21.32) ; U14.4 13.03,24.95 v1(13.08,25)
  BOTTOM w0.173: v1(13.08,25) 12.97,24.89 C145.1 12.18,24.88 11.59,24.29 11.59,22.82 R179.2 C138.1 12.97,21.21 v1(13.08,21.32)
N17004200: length 2.1
  TOP w0.173: v1(15.52,21.41) 15.38,21.27 U13.3
  BOTTOM w0.173: R180.1 14.79,21.97 15.35,21.41 v1(15.52,21.41)
N17004297: length 1.8
  TOP w0.173: U14.3 15.48,24.95 v1(15.53,25)
  BOTTOM w0.173: v1(15.53,25) 15.51,25.02 R181.1
N17012559: length 6.4
  BOTTOM w0.173: R239.2 119.38,22.6 119.13,22.86 119.13,25.02 119.38,25.27 U18.1
N17012562: length 5.9
  BOTTOM w0.173: U18.4 119.55,29.08 119.38,29.25 119.38,31.55 119.58,31.75 R240.2
N17015515: length 2.8
  BOTTOM w0.173: U19.1 119.63,36.07 119.38,36.32 119.38,36.82 R245.2
N17015527: length 2.8
  BOTTOM w0.173: 120.69,39.88 119.76,39.88 119.51,39.62 119.51,39.25 R246.2

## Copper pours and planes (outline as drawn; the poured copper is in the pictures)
12V on TOP: 31.75,64.49 30.86,64.49 30.86,65.4 30.66,65.61 30.3,65.61 30.3,67.31 30.05,67.56 26.16,67.56 25.93,67.33 25.93,64.49 24.99,64.49 24.99,65.43 24.82,65.61 24.43,65.61 24.43,67.36 24.23,67.56 21.31,67.56 20.95,67.21 20.95,64.72 20.7,64.46 19.18,64.46 19.18,65.45 19.02,65.61 18.64,65.61 18.64,66.22 18.39,66.47 18.39,67.79 18.14,68.05 17.53,68.05 17.53,69.87 20.85,69.87 21.31,69.42 31.83,69.42 31.83,64.57
12V on TOP: 13.03,64.49 12.88,64.64 12.88,65.15 13.06,65.33 15.32,65.33 15.44,65.45 15.44,65.89 15.65,66.09 16.26,66.09 16.46,65.89 16.46,64.79 16.23,64.57 15.82,64.57 15.7,64.44 15.7,63.7 15.57,63.58 15.04,63.58 14.88,63.73 14.88,64.36 14.76,64.49
12V on BOTTOM: 25.4,42.42 25.47,42.24 25.65,42.16 26.72,42.16 26.9,42.24 26.97,42.42 26.97,42.49 26.9,42.67 26.72,42.75 25.65,42.75 25.47,42.67 25.4,42.49
12V on BOTTOM: 21.06,64.69 21.06,68.2 20.8,68.45 19.43,68.45 19.43,67.44 19.28,67.28 18.39,67.28 18.19,67.08 18.19,65.71 18.36,65.53 19.99,65.53 20.17,65.35 20.17,64.69 20.29,64.57 20.93,64.57
12V on BOTTOM: 31.34,23.32 33.02,23.32 33.2,23.14 33.2,20.85 33.07,20.73 32.77,20.73 32.61,20.88 32.61,22.33 32.44,22.5 31.34,22.5
12V on BOTTOM: 16.38,64.34 16.56,64.51 16.56,65.91 16.31,66.17 15.95,66.17 15.8,66.01 15.8,65.2 15.67,65.07 11.43,65.07 11.2,64.85 11.2,63.68 11.3,63.58 15.27,63.58 15.47,63.78 15.47,64.21 15.6,64.34
12V on ART04: 20.85,52.55 21.46,51.94 26.47,51.94 26.87,51.54 26.87,48.97 27.41,48.44 35.92,48.44 35.93,48.42 37.55,48.42 37.82,48.16 37.82,42.49 37.8,42.47 37.8,24.94 38.28,24.46 74.55,24.46 74.93,24.08 74.93,17.04 75.16,16.81 111.35,16.81 111.73,17.19 111.73,20.5 112.14,20.9 115.19,20.9 116.41,22.12 116.41,34.54 116.79,34.92 116.79,35 122.1,35 122.56,35.46 122.56,47.88 122.86,48.18 124.33,48.18 124.56,47.95 124.56,32.92 124.16,32.51 121.34,32.51 120.65,31.83 120.65,18.92 119.84,18.11 115.8,18.11 115.27,17.58 115.27,13.82 114.88,13.44 72.14,13.44 71.7,13.87 71.7,19.99 71.07,20.62 32.92,20.62 32.54,21 32.54,23.49 32.55,23.51 32.55,40.83 32.33,41.05 25.81,41.05 25.32,41.53 25.32,42.75 24.99,43.08 21.29,43.08 20.88,43.48 20.88,46.32 17.2,50 13.53,50 13.51,49.99 12.9,49.99 12.7,50.19 12.7,67.18 13.16,67.64 22.05,67.64 22.48,67.21 22.48,63.3 20.85,61.67
12V_IN on TOP: 9.83,58.34 3.43,58.34 2.95,58.83 2.95,70.41 3.33,70.79 6.88,70.79 8.86,72.77 8.86,78.74 9.27,79.15 9.27,80.69 9.55,80.97 19.2,80.97 19.56,80.62 19.56,74.8 19.91,74.45 20.83,74.45 20.83,72.59 20.33,72.1 20.32,72.11 14.43,72.11 10.01,67.69 5.36,67.69 5.03,67.36 5.03,62.58 5.46,62.15 9.83,62.15
GND on BOTTOM: 2,8.51 0.95,8.94 0.51,10 0.51,85 0.95,86.05 2,86.49 23.85,86.49 23.85,77.69 38.86,77.69 38.86,86.49 47.29,86.49 47.29,85.52 47.42,85.52 47.42,86.49 127.5,86.49 128.55,86.05 128.99,85 128.99,10 128.55,8.94 127.5,8.51 ; 226 cut-outs
GND on GND02: 2,8.51 0.95,8.94 0.51,10 0.51,85 0.95,86.05 2,86.49 23.85,86.49 23.85,77.69 38.86,77.69 38.86,86.49 127.5,86.49 128.55,86.05 128.99,85 128.99,10 128.55,8.94 127.5,8.51 ; 1 cut-out
GND on ART03: 0.51,85 0.95,86.05 2,86.49 23.85,86.49 23.85,77.69 38.86,77.69 38.86,86.49 127.5,86.49 128.55,86.05 128.99,85 128.99,10 128.55,8.94 127.5,8.51 2,8.51 0.95,8.94 0.51,10 ; 1 cut-out
GND on ART04: 2,8.51 0.95,8.94 0.51,10 0.51,85 0.95,86.05 2,86.49 23.85,86.49 23.85,82.06 23.16,81.38 23.16,75.36 23.7,74.83 26.31,74.83 26.85,74.29 26.85,72.47 27.36,71.96 35.81,71.96 36.35,72.49 36.35,73.99 37.13,74.78 38.73,74.78 38.79,74.73 38.99,74.73 39.55,75.28 39.55,81.81 38.86,82.5 38.86,86.49 127.5,86.49 128.55,86.05 128.99,85 128.99,10 128.55,8.94 127.5,8.51 ; 2 cut-outs
GND on ART04: 38.61,48.39 64.77,48.39 66.34,49.96 66.34,65.43 66.67,65.76 74.7,65.76 75.26,65.2 75.26,29.79 74.9,29.44 64.77,29.44 64.34,29.01 64.34,25.25 64.03,24.94 38.58,24.94 38.33,25.2 38.33,48.11
GND on ART04: 113.41,52.83 116.38,52.83 116.66,52.55 116.66,42.32 116.2,41.86 114.53,41.86 114.3,41.63 114.3,38.35 114.63,38.02 121.39,38.02 121.87,37.54 121.87,35.71 121.49,35.33 116.18,35.33 115.7,34.85 115.7,33.4 115.72,33.37 115.72,22.17 115.01,21.46 113.72,21.46 113.69,21.49 111.4,21.49 111,21.08 111,18.95 111.02,18.92 111.02,17.73 110.59,17.3 105.13,17.3 104.67,17.75 104.67,43.59 105.54,44.45 112.55,44.45 113.23,45.13 113.23,52.65
VCC3V3_SD on ART04: 75.64,29.64 75.64,65.43 74.93,66.14 66.6,66.14 66.27,66.47 66.27,72.52 66.42,72.67 68.17,72.67 68.35,72.49 68.35,69.65 68.58,69.42 78.64,69.42 78.92,69.14 78.92,31.42 79.38,30.96 81.64,30.96 82.27,30.33 84.07,30.33 84.18,30.22 84.18,29.49 84.05,29.36 75.92,29.36
VCC3V3_WIFI on TOP: 103.41,57.23 101.32,57.23 101.15,57.4 101.15,61.87 100.92,62.1 99.24,62.1 99.24,61.29 99.67,61.29 99.85,61.11 99.85,56.59 103.41,56.59
VCC3V3_WIFI on TOP: 101.29,68.91 101.47,68.83 102.62,68.83 102.8,68.91 102.87,69.09 102.8,69.27 102.62,69.34 101.47,69.34 101.29,69.27 101.22,69.09
VCC3V3_WIFI on ART04: 102.74,70.94 102.97,70.71 102.97,58.47 103.66,57.78 116.18,57.78 116.19,57.77 118.83,57.77 119.02,57.58 119.02,53.64 118.75,53.36 96.7,53.36 96.67,53.34 95.17,53.34 94.79,53.72 94.79,70.66 95.07,70.94
VCC5V0_SYS on TOP: 83.85,22.07 85.39,22.07 85.57,22.15 85.65,22.33 85.65,24.33 85.57,24.51 85.39,24.59 82.85,24.59 82.68,24.51 82.6,24.33 82.6,23.19 82.75,23.04 83.57,23.04 83.69,22.91 83.69,22.22
VCC5V0_SYS on TOP: 31.24,57.33 28.63,57.33 28.35,57.05 28.35,55.45 28.12,55.22 27.53,55.22 27.3,54.99 27.3,51.64 27.53,51.41 29.79,51.41 30.02,51.64 30.02,55.7 30.25,55.93 31.24,55.93
VCC5V0_SYS on ART04: 82.22,71.7 81.86,72.06 71.09,72.06 70.18,72.97 66.27,72.97 65.89,72.59 65.89,50.42 64.31,48.84 27.76,48.84 27.23,49.38 27.23,54.76 27.56,55.09 53.21,55.09 53.23,55.1 58.98,55.1 59.54,55.66 59.54,79.22 60.07,79.75 87.25,79.75 88.06,78.94 88.06,45.03 88.49,44.6 97.56,44.6 97.94,44.22 97.94,21.08 97.52,20.66 82.5,20.66 82.22,20.94 82.22,24.66 82.55,24.99 84.38,24.99 84.73,25.35 84.73,33.55 84.56,33.73 82.5,33.73 82.22,34.01
VCC5V0_USB on TOP: 23.16,55.42 23.16,59.56 21.51,59.56 21.36,59.41 21.36,52.65 21.62,52.4 24.05,52.4 24.05,55.22 23.37,55.22
VCC5V0_USB on TOP: 109.3,47.75 109.37,47.57 109.55,47.5 111.58,47.5 111.76,47.57 111.84,47.75 111.84,48.77 111.76,48.95 111.58,49.02 109.55,49.02 109.37,48.95 109.3,48.77
VCC5V0_USB on BOTTOM: 76.81,83.07 75.67,83.07 75.46,83.27 75.46,84.84 75.67,85.05 77.98,85.05 78.13,84.9 78.13,84.46 77.93,84.26 77.06,84.26 76.81,84.01
VCC5V0_USB on ART04: 88.79,45 88.42,45.36 88.42,79.93 88.19,80.16 61.54,80.16 61.53,80.15 59.4,80.15 59.05,79.81 59.05,56.16 58.29,55.4 27,55.4 26.47,54.86 26.47,52.88 25.98,52.4 21.69,52.4 21.44,52.65 21.44,59.84 21.45,59.85 21.45,61.35 22.48,62.38 52.76,62.38 53.39,63.02 53.39,84.73 53.75,85.09 93.9,85.09 94.34,84.66 94.34,84.16 94.39,84.11 94.39,53.11 94.67,52.83 112.47,52.83 112.75,52.55 112.75,45.87 111.87,45
VCC5V0_USB20_HUB on TOP: 103.25,73.15 103.76,73.15 103.94,72.97 103.94,71.73 103.78,71.58 102.18,71.58 102.18,72.16 102.95,72.16 103.1,72.31 103.1,73
VCC5V0_USB20_HUB on TOP: 122.58,38.76 118.85,38.76 118.75,38.86 118.75,39.5 118.49,39.75 115.19,39.75 114.94,39.5 114.94,38.99 115.06,38.86 117.35,38.86 117.6,38.61 117.6,37.97 117.73,37.84 122.58,37.84
VCC5V0_USB20_HUB on TOP: 112.37,48.26 114.35,48.26 114.58,48.49 114.58,48.82 119.33,48.82 119.61,49.1 119.61,51.03 122.58,51.03 122.58,47.9 122.33,47.65 112.37,47.65
VCC5V0_USB20_HUB on BOTTOM: 118.95,80.17 119.02,79.99 119.2,79.92 121.06,79.92 121.24,79.99 121.31,80.17 121.31,80.3 121.24,80.48 121.06,80.55 119.2,80.55 119.02,80.48 118.95,80.3
VCC5V0_USB20_HUB on ART04: 114.68,38.4 121.23,38.4 121.87,39.04 121.87,47.85 122.83,48.82 122.83,80.39 122.53,80.69 112.8,80.69 111.79,79.68 111.79,74.85 111.33,74.4 103.94,74.4 103.33,73.79 103.33,58.67 103.84,58.16 119.33,58.16 119.48,58.01 119.48,53.29 119.15,52.96 117.46,52.96 117.21,52.7 117.21,41.77 116.71,41.27 114.83,41.27 114.6,41.05 114.58,41.05 114.58,38.51 ; 1 cut-out
VCCA_1V8 on TOP: 63.7,14.93 63.7,17.91 63.5,18.11 63.14,18.11 62.92,18.34 62.92,19.51 63.07,19.66 64.47,19.66 64.62,19.51 64.62,14.93
VCCA_1V8 on TOP: 84.89,29.01 82.65,29.01 82.5,28.85 82.5,27.58 82.63,27.46 82.85,27.46 83.11,27.71 83.11,28.42 83.29,28.6 84.89,28.6
VCCA_1V8 on BOTTOM: 64.82,25.07 64.9,24.89 65.07,24.81 65.18,24.81 65.36,24.89 65.43,25.07 65.43,26.21 65.36,26.39 65.18,26.47 65.07,26.47 64.9,26.39 64.82,26.21
VCCA_1V8 on BOTTOM: 62.89,18.41 62.96,18.23 63.14,18.16 63.2,18.16 63.37,18.23 63.45,18.41 63.45,19.46 63.37,19.63 63.2,19.71 63.14,19.71 62.96,19.63 62.89,19.46
VCCA_1V8 on ART04: 64.87,25.14 65.18,24.84 75.03,24.84 75.41,24.46 75.41,17.73 75.74,17.4 103.76,17.4 104.24,17.88 104.24,43.99 103.76,44.47 98.6,44.47 98.35,44.22 98.35,20.67 97.99,20.32 82.14,20.32 81.79,20.67 81.79,24.71 82.35,25.27 83.64,25.27 84.15,25.78 84.15,28.83 83.92,29.06 65.38,29.06 64.87,28.55
VCCIO_ACODEC on ART04: 84.2,30.71 84.2,32.94 83.9,33.25 82.04,33.25 81.86,33.43 81.86,71.27 81.56,71.58 70.13,71.58 69.95,71.75 69.95,72.52 69.8,72.67 68.94,72.67 68.76,72.49 68.76,70.2 68.99,69.98 78.94,69.98 79.27,69.65 79.27,31.44 79.5,31.22 82.02,31.22 82.73,30.5 84,30.5
VDD_3V3 on TOP: 122.76,16.71 122.76,16.05 122.56,15.85 121.82,15.85 121.72,15.75 121.72,15.14 121.79,15.06 123.29,15.06 123.37,15.14 123.37,16.71
VDD_3V3 on TOP: 18.21,43.61 17.45,43.61 17.25,43.41 17.25,39.88 17.5,39.62 18.14,39.62 18.62,39.14 18.62,37.79 19.23,37.79 19.23,39.45 18.21,40.46 18.21,41.5 18.39,41.68 18.87,41.68 18.97,41.78 18.97,42.52 18.82,42.67 18.39,42.67 18.21,42.85
VDD_3V3 on TOP: 98.83,63.14 98.91,62.96 99.09,62.89 100.23,62.89 100.41,62.96 100.49,63.14 100.49,64.13 100.41,64.31 100.23,64.39 99.09,64.39 98.91,64.31 98.83,64.13
VDD_3V3 on TOP: 73.96,13.44 74.04,13.26 74.22,13.18 74.63,13.18 74.8,13.26 74.88,13.44 74.88,17.65 74.8,17.83 74.63,17.91 74.22,17.91 74.04,17.83 73.96,17.65
VDD_3V3 on TOP: 6.22,25.14 7.65,25.14 7.92,24.87 7.92,23.62 8.18,23.37 12.55,23.37 12.55,22.76 11.56,22.76 10.64,21.84 6.32,21.84 5.99,22.17 5.99,24.92
VDD_3V3 on TOP: 19.56,57.33 19.56,55.93 18.57,55.93 18.21,55.57 18.21,52.4 16.05,52.4 15.82,52.63 15.82,55.96 16,56.13 16.64,56.13 16.81,56.31 16.81,57.15 16.99,57.33
VDD_3V3 on BOTTOM: 74.09,12.65 74.17,12.47 74.35,12.39 74.5,12.39 74.68,12.47 74.75,12.65 74.75,14.55 74.68,14.73 74.5,14.81 74.35,14.81 74.17,14.73 74.09,14.55
VDD_3V3 on BOTTOM: 14.48,27.35 14.48,25.73 15.82,25.73 15.95,25.86 15.95,26.85 15.77,27.02 15.19,27.02 15.09,27.13 15.09,27.35
VDD_3V3 on PWR05: 2,8.51 0.95,8.94 0.51,10 0.51,85 0.95,86.05 2,86.49 23.85,86.49 23.85,77.69 38.86,77.69 38.86,86.49 127.5,86.49 128.55,86.05 128.99,85 128.99,10 128.55,8.94 127.5,8.51
VDD_5V on TOP: 11.02,19.33 11.1,19.15 11.28,19.07 12.37,19.07 12.55,19.15 12.62,19.33 12.62,20.37 12.55,20.55 12.37,20.62 11.28,20.62 11.1,20.55 11.02,20.37
VDD_5V on TOP: 12.88,52.42 12.88,55.09 12.75,55.22 12.06,55.22 11.81,55.47 11.81,59.56 10.41,59.56 10.41,55.4 10.24,55.22 9.88,55.22 9.73,55.07 9.73,52.7 10.03,52.4 12.85,52.4
VDD_5V on TOP: 10.59,37.9 10.59,36.6 10.44,36.45 6.71,36.45 6.38,36.12 6.38,27.1 6.53,26.95 10.64,26.95 10.74,26.85 10.74,25.09 10.64,24.99 9.88,24.99 9.73,25.14 9.73,25.78 9.55,25.96 6.15,25.96 5.69,26.41 5.69,37.69 6.05,38.05 10.44,38.05
VDD_5V on TOP: 123.77,15.44 123.85,15.26 124.03,15.19 125.12,15.19 125.3,15.26 125.37,15.44 125.37,16.43 125.3,16.61 125.12,16.69 124.03,16.69 123.85,16.61 123.77,16.43
VDD_5V on BOTTOM: 14.71,41.88 14.71,40.92 14.96,40.66 16.69,40.66 16.84,40.82 16.84,42.24 16.59,42.49 15.67,42.49 15.52,42.65 15.52,43.41 12.4,43.41 10.87,41.88 10.87,38.48 10.59,38.2 10.03,38.2 9.86,38.02 9.86,37.69 9.68,37.51 8.97,37.51 8.97,36.55 9.12,36.4 11.53,36.4 11.94,36.8 11.94,41.68 12.42,42.16 14.43,42.16
VDD_5V on BOTTOM: 8.97,25.6 8.97,26.54 9.09,26.67 10.44,26.67 10.62,26.49 10.62,25.12 10.46,24.97 10.13,24.97 9.98,25.12 9.98,25.45 9.83,25.6
VDD_5V on ART04: 24.69,42.8 24.94,42.54 24.94,41.68 25.83,40.79 27.13,40.79 27.18,40.84 31.72,40.84 32.13,40.44 32.13,20.78 32.66,20.24 70.84,20.24 71.27,19.81 71.27,13.28 71.63,12.93 115.19,12.93 115.72,13.46 115.72,17.3 116.03,17.6 120.14,17.6 121.11,18.57 121.11,31.75 121.39,32.03 124.87,32.03 125.15,32.31 125.15,48.16 124.87,48.44 123.52,48.44 123.24,48.72 123.24,49.71 123.52,49.99 126.92,49.99 127.41,49.5 127.41,15.59 126.9,15.09 119.48,15.09 119.08,14.68 119.08,10.84 118.54,10.31 68.45,10.31 68.25,10.51 68.25,11.2 68.28,11.23 68.28,17.12 67.89,17.5 29.92,17.5 29.59,17.83 29.59,18.59 29.26,18.92 29.26,22.38 28.6,23.04 17.7,23.04 17.2,23.54 17.2,30.48 16.31,31.37 16.31,44.63 14.81,46.13 7.62,46.13 6.99,46.76 6.99,55.07 7.32,55.4 9.25,55.4 9.68,55.83 9.68,65.94 10.03,66.29 11.91,66.29 12.34,65.86 12.34,49.99 12.75,49.58 14.96,49.58 14.99,49.55 16.99,49.55 20.62,45.92 20.62,43.36 21.18,42.8
VDD_5V on ART04: 9.25,26.62 11.38,26.62 11.81,26.19 11.81,21.64 12.04,21.41 12.6,21.41 12.83,21.18 12.85,21.18 12.85,20.01 12.6,19.76 9.12,19.76 8.94,19.94 8.94,26.31
VDD_CAM0_5V on BOTTOM: 7.21,21.72 7.21,22 7.39,22.17 8.36,22.17 8.56,22.38 8.56,26.21 7.98,26.21 7.98,23.14 7.85,23.01 5.92,23.01 5.92,21.72
VDD_CAM1_5V on BOTTOM: 5.89,40.41 8.36,40.41 8.56,40.21 8.56,36.91 7.98,36.91 7.98,38.96 7.82,39.11 5.89,39.11
VDD_CAM2_5V on BOTTOM: 5.89,57.81 7.75,57.81 7.98,58.04 7.98,59.87 8.56,59.87 8.56,56.74 8.31,56.49 5.89,56.49
VDD_CAM3_5V on BOTTOM: 8.56,70.94 8.56,74.95 8.33,75.18 5.89,75.18 5.89,73.86 7.82,73.86 7.98,73.71 7.98,70.94
VDD_IO on TOP: 122.61,22.5 122.61,17.88 122.78,17.7 124.38,17.7 124.38,17.09 121.74,17.09 121.74,21.28 121.44,21.59 119.58,21.59 119.58,22.5
VDD_LCD_3V3 on TOP: 13.87,23.37 15.11,23.37 15.29,23.54 15.29,24.15 15.42,24.28 15.77,24.28 15.95,24.1 15.95,22.78 15.82,22.66 13.94,22.66 13.87,22.73
VDD_LCD_3V3 on BOTTOM: 14.48,22.94 14.55,22.76 14.73,22.68 15.65,22.68 15.83,22.76 15.9,22.94 15.9,24.08 15.83,24.26 15.65,24.33 14.73,24.33 14.55,24.26 14.48,24.08
VDD_LCD_3V3 on BOTTOM: 64.34,16.56 64.01,16.23 64.01,13.84 64.82,13.84 64.82,15.72 65.05,15.95 68.12,15.95 68.12,16.56
VDD_LCD_3V3 on ART04: 67.64,17.07 67.84,16.86 67.84,15.95 67.59,15.7 66.09,15.7 65.84,15.44 65.84,13.59 65.61,13.36 24.41,13.36 24.08,13.69 24.08,19.2 23.55,19.73 14.76,19.73 14.27,20.22 14.27,24.13 14.48,24.33 15.67,24.33 15.85,24.15 15.85,22.91 16.21,22.55 27.89,22.55 27.91,22.53 28.5,22.53 28.87,22.16 28.87,18.33 29.11,18.08 29.11,17.47 29.54,17.04 29.57,17.04 29.59,17.07
VDD_LCD_5V on TOP: 15.98,19.89 15.75,19.66 13.87,19.66 13.87,19.07 16.21,19.07 16.38,18.9 16.41,18.9 16.43,18.87 16.43,13.36 16.79,13 18.82,13 18.97,13.16 18.97,13.49 18.77,13.69 17.35,13.69 17.2,13.84 17.2,17.83 17.83,18.46 17.83,19.89
VDD_LCD_5V on BOTTOM: 65.02,14.12 65.1,13.94 65.28,13.87 68.96,13.87 69.14,14.05 69.14,14.78 69.29,14.93 69.9,14.93 69.9,15.54 65.13,15.54 65.02,15.44
VDD_LCD_5V on ART04: 24.18,13.03 65.79,13.03 66.19,13.44 66.19,15.24 66.47,15.52 67.44,15.52 67.84,15.11 67.84,10.31 67.39,9.85 17.73,9.85 17.37,10.21 17.37,13.26 17.68,13.56 17.68,13.59 23.62,13.59
VDD_LVDS on TOP: 22.35,24 21.54,24 21.54,22.1 21.34,21.89 17.22,21.89 17.22,21.28 23.14,21.28 23.24,21.39 23.24,23.11 23.04,23.11 23.04,21.79 22.99,21.74 22.4,21.74 22.33,21.82 22.33,23.98
VDD_LVDS on BOTTOM: 11.89,28.24 11.89,25.6 13.13,25.6 13.28,25.75 13.28,26.95 13.11,27.13 12.65,27.13 12.47,27.3 12.47,28.24
VDDIO_LVDS on TOP: 28.04,30.02 28.91,30.02 29.29,30.4 29.59,30.4 29.77,30.22 29.77,29.95 29.03,29.21 28.04,29.21
(no net) on TOP: 0.51,85 0.95,86.05 2,86.49 23.85,86.49 23.85,77.69 38.86,77.69 38.86,86.49 127.5,86.49 128.55,86.05 128.99,85 128.99,10 128.55,8.94 127.5,8.51 2,8.51 0.95,8.94 0.51,10 ; 214 cut-outs
LVDS_5V on BOTTOM: 27.33,20.9 27.33,21.77 27.2,21.89 24.33,21.89 24.33,21.31 26.37,21.31 26.52,21.16 26.52,20.9
LVDS_12V on TOP: 5.18,40.61 5.26,40.43 5.44,40.36 9.65,40.36 9.83,40.43 9.91,40.61 9.91,43.03 9.83,43.21 9.65,43.28 5.44,43.28 5.26,43.21 5.18,43.03
LVDS_12V on BOTTOM: 27.89,21.89 31.98,21.89 32.16,21.72 32.16,20.75 32.03,20.62 29.11,20.62 29.11,21.18 28.98,21.31 27.89,21.31
LVDS_12V on ART04: 6.15,19.71 6.15,43 5.79,43.36 2.92,43.36 2.57,43 2.57,16.64 3.15,16.05 16.81,16.05 17.14,16.38 17.14,19 16.89,19.25 6.6,19.25
USB30_OTG_VBUS on BOTTOM: 80.19,82.2 76.45,82.2 76.23,81.97 76.23,80.55 79.93,80.55 80.19,80.81
N16722097 on TOP: 28.45,61.57 28.52,61.39 28.7,61.31 29.26,61.31 29.44,61.39 29.51,61.57 29.51,63.04 29.44,63.22 29.26,63.3 28.7,63.3 28.52,63.22 28.45,63.04
N16722109 on TOP: 31.75,64.24 30,64.24 29.82,64.06 29.82,61.14 29.62,60.93 28.96,60.93 28.96,59.51 31.24,59.51 31.24,62.13 31.06,62.31 30.68,62.31 30.53,62.46 30.53,63.37 30.71,63.55 31.75,63.55
N16722987 on TOP: 20.07,64.24 18.34,64.24 18.14,64.03 18.14,61.19 17.86,60.91 17.27,60.91 17.27,59.51 19.56,59.51 19.56,60.91 19.18,60.91 18.92,61.16 18.92,63.45 19.05,63.58 20.07,63.58
N16723079 on TOP: 16.76,61.57 16.84,61.39 17.02,61.31 17.58,61.31 17.76,61.39 17.83,61.57 17.83,63.04 17.76,63.22 17.58,63.3 17.02,63.3 16.84,63.22 16.76,63.04
N16723587 on TOP: 11.25,61.54 11.33,61.36 11.51,61.29 12.06,61.29 12.24,61.36 12.32,61.54 12.32,63.04 12.24,63.22 12.06,63.3 11.51,63.3 11.33,63.22 11.25,63.04
N16723611 on TOP: 14.55,64.24 12.78,64.24 12.62,64.08 12.62,60.6 12.85,60.37 13.72,60.37 14.02,60.07 14.02,57.28 15.39,57.28 15.39,61.29 15.27,61.42 13.44,61.42 13.26,61.59 13.26,63.37 13.44,63.55 14.55,63.55
N16724119 on TOP: 22.61,61.57 22.68,61.39 22.86,61.31 23.42,61.31 23.6,61.39 23.67,61.57 23.67,63.04 23.6,63.22 23.42,63.3 22.86,63.3 22.68,63.22 22.61,63.04
N16724131 on TOP: 25.91,64.24 24.18,64.24 23.98,64.03 23.98,60.55 24.13,60.4 25.2,60.4 25.35,60.25 25.35,57.28 26.77,57.28 26.77,61.21 26.59,61.39 24.87,61.39 24.69,61.57 24.69,63.4 24.84,63.55 25.91,63.55
N16783279 on BOTTOM: 13.54,37.06 13.54,38.53 27,38.53 27.2,38.33 27.2,37.67 24.66,37.67 24.33,37.34 24.33,36.7 24.31,36.68 13.92,36.68
N16783471 on BOTTOM: 16.92,44.22 16.92,47.12 8.46,47.12 8.46,44.19 8.79,43.86 12.65,43.86 12.88,44.09 12.88,45.54 13.03,45.69 14.53,45.69 14.73,45.49 14.73,44.22

Small or netless copper shapes (teardrops, artwork), in the pictures only: 26 on TOP, 37 on BOTTOM, 12 on ART03

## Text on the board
Ref Des/Silkscreen Bottom: VCC | 3V3 | 5V | 12V | 1 | 2 | J18 | MIPI_DSI | 20241202 | EBF410347V1R0 | J24 | J29 | J30 | J28 | CAM3 | CAM2 | CAM1 | CAM0 | 30 | 29 | D3N | D3P | CKN | CKP | GND | D2N | D2P | D1N | D1P | D0N | D0P | KEY | RST | 1_OUT | REC | 1_IN | 2_OUT | 1V8 | 2_IN | O_IN5 | 0_IN6 | 0_IN7 | 1_IN6 | 1_IN7 | 2_B | 2_A
Ref Des/Silkscreen Top: GND | RX | J31 | DC_12V | TX | J2 | J1 | J20 | J10 | J17 | EBF410347V1R0 | 20241202 | ENT0 | LVDS | JLCJLCJLCJLCJLCJLC | J5 | PH0NE | 1 | J7 | SARADC1 | TF CARD | J26 | J9 | LED/IR | USB3.0_OTG | J21 | RS232_1 | KEY | J34 | J16 | J32 | USB HUB1 | RS232_2 | J12 | J37 | J35 | SARADC0 | J13 | RS485_2 | RS485_1 | USB HUB2 | J27 | J36 | J33 | J38 | J14 | J23 | RTC | J25 | J22 | FAN | PWR | SYS | J15 | LVDS_BL | CPT | SPK | J8 | J19 | MIC | PHSPK | J6 | J11 | J4 | USB HUB3 | USB HUB4 | IO/CAN | MR | RK3562
DIMENSION: GND | RX | TX | DC_12V | LVDS_12V | LVDS_3V3 | LVDS_5V | 29 | 30 | VCC_LVDS | LVDS | ENT0 | 2 | 1 | 19 | 20 | GPIO | PHONE | KEY | USB1 | LED/IR | IO | USB2 | OTG | J4 | L2 | D5 | D6 | J2 | J19 | J23 | J22 | L13 | C101 | C102 | L14 | C141 | C142 | R161 | U3 | C91 | C90 | L11 | C11 | L10 | J26 | F1 | R6 | LED1 | J1 | R100 | C4 | C2 | L1 | C143 | C144 | U10 | C3 | R90 | C89 | C92 | R94 | R92 | R99 | C100 | C103 | C1 | U1 | Y5 | U9 | L3 | C8 | D7 | C7 | U2 | U20 | L4 | C20 | C18 | J20 | U4 | C21 | J5 | C74 | C140 | C125 | C128 | C121 | C123 | C127 | R156 | R157 | R158 | R155 | R154 | C19 | C137 | C138 | J28 | J16 | J27 | J13 | J14 | J3 | J10 | J24 | D19 | Y4 | C46 | D20 | R38 | R37 | R39 | R36 | C42 | R35 | C43 | R119 | R116 | C45 | L15 | U14 | Y2 | U19 | U18 | J6 | C44 | J18 | C113 | C114 | C115 | C116 | R40 | C47 | C39 | C50 | C104 | R48 | R45 | R113 | R112 | U12 | C36 | C35 | C49 | R111 | R108 | R109 | D18 | C32 | C33 | J8 | J11 | J25 | L6 | J12 | J7 | LVDS_BL | SPK | CPT | SD | MIC | FAN | RTC | USB3 | USB4 | C13 | SS3 | SS2 | C12 | U16 | U17 | U21 | L5 | R101 | R89 | R98 | C87 | C99 | R167 | R159 | R149 | R148 | R145 | R146 | R144 | R141 | R139 | R140 | R153 | R152 | C27 | R150 | R151 | D8 | R137 | R135 | R133 | R142 | R132 | R131 | R82 | R129 | R130 | L17 | C139 | D43 | R124 | R123 | R125 | C110 | C111 | C41 | C109 | R163 | R43 | R121 | D44 | R41 | R122 | R164 | C40 | D45 | R120 | C51 | D46 | R118 | R166 | C106 | D47 | J17 | D48 | C34 | R29 | D49 | C105 | D25 | D26 | D50 | R30 | CN1 | SS1 | SS4 | EBF410335 | 20230817 | RK3128 | 86 | 126.5
User.8: FIGURE | SIZE | 10.0 | 19.689 | 25.591 | 27.559 | 31.496 | 31.5 | 35.429 | 39.37 | 90.551 | 122.051 | 47.24 | 78.701 | 59.059x29.531 | 66.902x19.701 | 70.902x15.701 | 94.488x39.37 | DRILL CHART: TOP to BOTTOM | ALL UNITS ARE IN MILS | PLATED | NON-PLATED | QTY | 1432 | 2 | 9 | 28 | 12 | 36 | 8 | 5 | 4 | 1 | 7 | 3
